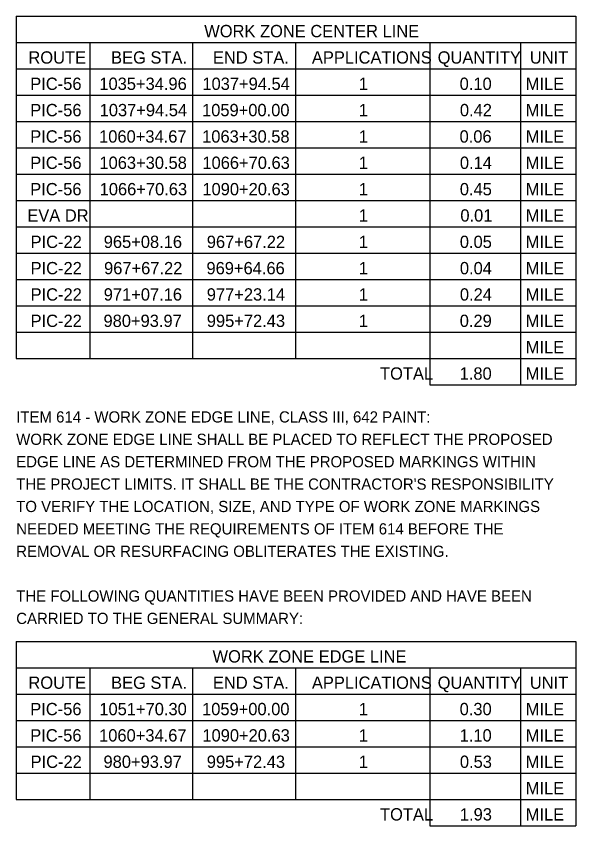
# Model space of a CAD drawing. Extents: x 37613.4 to 37668.4, y 18853.7 to 18946.8.
# Drawn here: x 37646.22 to 37653.22, y 18853.7 to 18863.83 of the extents above; entities that cross this region are included whole.
import ezdxf

# ---------------------------------------------------------------- set-up
doc = ezdxf.new("R2010")
doc.units = 0
doc.layers.add('SH_Data', color=7, linetype='Continuous')
doc.layers.add('SH_Text', color=7, linetype='Continuous')

msp = doc.modelspace()

# ---------------------------------------------------------------- linework, layer by layer
at = {"layer": 'SH_Data'}
for p, q in [((37646.221, 18863.825), (37653.221, 18863.825)), ((37646.221, 18863.825), (37646.221, 18859.543)), ((37653.221, 18863.825), (37653.221, 18859.214)), ((37646.221, 18863.496), (37653.221, 18863.496)), ((37647.143, 18863.496), (37647.143, 18859.543)), ((37648.428, 18863.496), (37648.428, 18859.543)), ((37649.713, 18863.496), (37649.713, 18859.543)), ((37651.393, 18863.496), (37651.393, 18859.214)), ((37652.529, 18863.496), (37652.529, 18859.214)), ((37646.221, 18863.166), (37653.221, 18863.166)), ((37646.221, 18862.837), (37653.221, 18862.837)), ((37646.221, 18862.508), (37653.221, 18862.508)), ((37646.221, 18862.178), (37653.221, 18862.178)), ((37646.221, 18861.849), (37653.221, 18861.849)), ((37646.221, 18861.519), (37653.221, 18861.519)), ((37646.221, 18861.19), (37653.221, 18861.19)), ((37646.221, 18860.861), (37653.221, 18860.861)), ((37646.221, 18860.531), (37653.221, 18860.531)), ((37646.221, 18860.202), (37653.221, 18860.202)), ((37646.221, 18859.872), (37653.221, 18859.872)), ((37646.221, 18859.543), (37653.221, 18859.543)), ((37651.393, 18859.214), (37653.221, 18859.214)), ((37646.221, 18856.005), (37653.221, 18856.005)), ((37646.221, 18856.005), (37646.221, 18854.028)), ((37653.221, 18856.005), (37653.221, 18853.699)), ((37646.221, 18855.675), (37653.221, 18855.675)), ((37647.143, 18855.675), (37647.143, 18854.028)), ((37648.428, 18855.675), (37648.428, 18854.028)), ((37649.713, 18855.675), (37649.713, 18854.028)), ((37651.393, 18855.675), (37651.393, 18853.699)), ((37652.529, 18855.675), (37652.529, 18853.699)), ((37646.221, 18855.346), (37653.221, 18855.346)), ((37646.221, 18855.016), (37653.221, 18855.016)), ((37646.221, 18854.687), (37653.221, 18854.687)), ((37646.221, 18854.358), (37653.221, 18854.358)), ((37646.221, 18854.028), (37653.221, 18854.028)), ((37651.393, 18853.699), (37653.221, 18853.699))]:
    msp.add_line(p, q, dxfattribs=at)

# ---------------------------------------------------------------- texts
for s, p in [('WORK ZONE CENTER LINE', (37648.573, 18863.562)), ('ROUTE', (37646.374, 18863.232)), ('BEG STA.', (37647.408, 18863.232)), ('END STA.', (37648.682, 18863.232)), ('APPLICATIONS', (37649.92, 18863.232)), ('QUANTITY', (37651.493, 18863.232)), ('UNIT', (37652.646, 18863.232)), ('PIC-56', (37646.397, 18862.903)), ('1035+34.96', (37647.261, 18862.903)), ('1037+94.54', (37648.55, 18862.903)), ('1', (37650.507, 18862.903)), ('0.10', (37651.768, 18862.903)), ('MILE', (37652.595, 18862.903)), ('PIC-56', (37646.397, 18862.574)), ('1037+94.54', (37647.265, 18862.574)), ('1059+00.00', (37648.546, 18862.574)), ('1', (37650.507, 18862.574)), ('0.42', (37651.771, 18862.574)), ('MILE', (37652.595, 18862.574)), ('PIC-56', (37646.397, 18862.244)), ('1060+34.67', (37647.258, 18862.244)), ('1063+30.58', (37648.547, 18862.244)), ('1', (37650.507, 18862.244)), ('0.06', (37651.767, 18862.244)), ('MILE', (37652.595, 18862.244)), ('PIC-56', (37646.397, 18861.915)), ('1063+30.58', (37647.262, 18861.915)), ('1066+70.63', (37648.55, 18861.915)), ('1', (37650.507, 18861.915)), ('0.14', (37651.771, 18861.915)), ('MILE', (37652.595, 18861.915)), ('PIC-56', (37646.397, 18861.585)), ('1066+70.63', (37647.265, 18861.585)), ('1090+20.63', (37648.55, 18861.585)), ('1', (37650.507, 18861.585)), ('0.45', (37651.77, 18861.585)), ('MILE', (37652.595, 18861.585)), ('EVA DR', (37646.36, 18861.256)), ('1', (37650.507, 18861.256)), ('0.01', (37651.777, 18861.256)), ('MILE', (37652.595, 18861.256)), ('PIC-22', (37646.401, 18860.926)), ('965+08.16', (37647.316, 18860.926)), ('967+67.22', (37648.605, 18860.926)), ('1', (37650.507, 18860.926)), ('0.05', (37651.77, 18860.926)), ('MILE', (37652.595, 18860.926)), ('PIC-22', (37646.401, 18860.597)), ('967+67.22', (37647.32, 18860.597)), ('969+64.66', (37648.601, 18860.597)), ('1', (37650.507, 18860.597)), ('0.04', (37651.771, 18860.597)), ('MILE', (37652.595, 18860.597)), ('PIC-22', (37646.401, 18860.268)), ('971+07.16', (37647.316, 18860.268)), ('977+23.14', (37648.605, 18860.268)), ('1', (37650.507, 18860.268)), ('0.24', (37651.771, 18860.268)), ('MILE', (37652.595, 18860.268)), ('PIC-22', (37646.401, 18859.938)), ('980+93.97', (37647.313, 18859.938)), ('995+72.43', (37648.605, 18859.938)), ('1', (37650.507, 18859.938)), ('0.29', (37651.769, 18859.938)), ('MILE', (37652.595, 18859.938)), ('MILE', (37652.595, 18859.609)), ('TOTAL', (37650.772, 18859.279)), ('1.80', (37651.768, 18859.279)), ('MILE', (37652.595, 18859.279)), ('WORK ZONE EDGE LINE', (37648.677, 18855.741)), ('ROUTE', (37646.374, 18855.412)), ('BEG STA.', (37647.408, 18855.412)), ('END STA.', (37648.682, 18855.412)), ('APPLICATIONS', (37649.92, 18855.412)), ('QUANTITY', (37651.493, 18855.412)), ('UNIT', (37652.646, 18855.412)), ('PIC-56', (37646.397, 18855.082)), ('1051+70.30', (37647.261, 18855.082)), ('1059+00.00', (37648.546, 18855.082)), ('1', (37650.507, 18855.082)), ('0.30', (37651.768, 18855.082)), ('MILE', (37652.595, 18855.082)), ('PIC-56', (37646.397, 18854.753)), ('1060+34.67', (37647.258, 18854.753)), ('1090+20.63', (37648.55, 18854.753)), ('1', (37650.507, 18854.753)), ('1.10', (37651.768, 18854.753)), ('MILE', (37652.595, 18854.753)), ('PIC-22', (37646.401, 18854.423)), ('980+93.97', (37647.313, 18854.423)), ('995+72.43', (37648.605, 18854.423)), ('1', (37650.507, 18854.423)), ('0.53', (37651.771, 18854.423)), ('MILE', (37652.595, 18854.423)), ('MILE', (37652.595, 18854.094)), ('TOTAL', (37650.772, 18853.765)), ('1.93', (37651.771, 18853.765)), ('MILE', (37652.595, 18853.765))]:
    msp.add_text(s, height=0.154, dxfattribs=at).set_placement(p)
at = {"layer": 'SH_Text'}
for s, p in [('ITEM 614 - WORK ZONE EDGE LINE, CLASS III, 642 PAINT:', (37646.221, 18858.743)), ('WORK ZONE EDGE LINE SHALL BE PLACED TO REFLECT THE PROPOSED ', (37646.221, 18858.463)), ('EDGE LINE AS DETERMINED FROM THE PROPOSED MARKINGS WITHIN ', (37646.221, 18858.183)), ("THE PROJECT LIMITS. IT SHALL BE THE CONTRACTOR'S RESPONSIBILITY ", (37646.221, 18857.903)), ('TO VERIFY THE LOCATION, SIZE, AND TYPE OF WORK ZONE MARKINGS ', (37646.221, 18857.623)), ('NEEDED MEETING THE REQUIREMENTS OF ITEM 614 BEFORE THE ', (37646.221, 18857.343)), ('REMOVAL OR RESURFACING OBLITERATES THE EXISTING.', (37646.221, 18857.063)), ('THE FOLLOWING QUANTITIES HAVE BEEN PROVIDED AND HAVE BEEN ', (37646.221, 18856.503)), ('CARRIED TO THE GENERAL SUMMARY:', (37646.221, 18856.223))]:
    msp.add_text(s, height=0.14, dxfattribs=at).set_placement(p)

doc.saveas('drawing.dxf')
